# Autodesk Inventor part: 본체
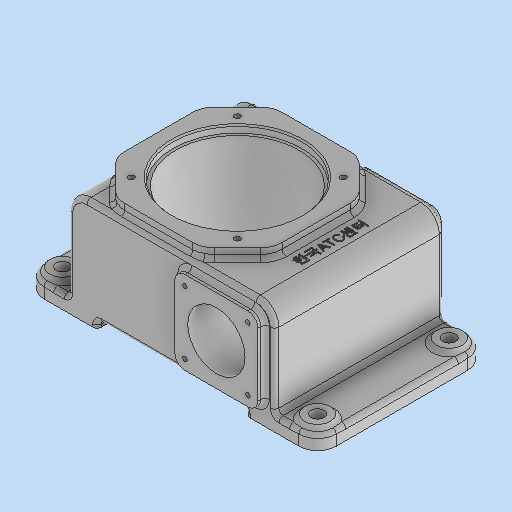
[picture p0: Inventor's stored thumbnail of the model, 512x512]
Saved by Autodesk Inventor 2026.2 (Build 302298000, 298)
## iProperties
Created: 2026-02
Part Number: 본체
Material: 일반
Document SubType Name: Modeling
Designer: PC2-07
Density: 1 g/cm^3
Appearance: 기본값
Author: PC2-07
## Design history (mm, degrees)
sketch "스케치1"
  geometry: L1 (102, -59)-(-102, -59); L2 (-102, -59)-(-102, 59); L3 (-102, 59)-(102, 59); L4 (102, 59)-(102, -59); L5 (102, -59)-(-102, 59); L6 (-102, -59)-(102, 59); L7 (-52, 59)-(-52, -59); L8 (52, 59)-(52, -59); 1 further point
  constraints: 16 end point, 4 point on line, 3 perpendicular, 2 midpoint, 2 parallel, 1 horizontal
  dimensions: "d0" = 118 distance between parallel lines of L1 L3; "d1" = 204 distance between parallel lines of L4 L2; "d2" = 50 distance between parallel lines of L2 L7; "d3" = 50 distance between parallel lines of L4 L8
extrude "돌출1" new body sketch "스케치1" distance "d4" = 10; taper "d5" = 0 deg
node "작업 평면1"
sketch "스케치2"
  geometry: L1 (72, -59)-(-72, -59); L2 (-72, -59)-(-72, 59); L3 (-72, 59)-(72, 59); L4 (72, 59)-(72, -59); L5 (72, -59)-(-72, 59); L6 (-72, -59)-(72, 59); 1 further point
  constraints: 12 end point, 2 midpoint, 2 parallel, 1 horizontal, 1 perpendicular
  dimensions: "d7" = 118 distance between parallel lines of L1 L3; "d8" = 144 distance between parallel lines of L4 L2
extrude "돌출2" join sketch "스케치2" distance "d9" = 70; taper "d10" = 0 deg
node "작업 평면2"
sketch "스케치3"
  geometry: L1 (-7.359, 69)-(-65.359, 69); L2 (-65.359, 69)-(-65.359, 11); L3 (-65.359, 11)-(-7.359, 11); L4 (-7.359, 11)-(-7.359, 69); L5 (-7.359, 69)-(-65.359, 11); L6 (-65.359, 69)-(-7.359, 11); 2 further points
  constraints: 12 end point, 2 midpoint, 2 parallel, 1 horizontal, 1 perpendicular
  dimensions: "d12" = 40 vertical distance of point (0, 0) point (-36.359, 40); "d13" = 58 distance between parallel lines of L3 L1; "d14" = 58 distance between parallel lines of L4 L2
extrude "돌출3" join sketch "스케치3" distance "d15" = 128; taper "d16" = 0 deg
sketch "스케치4"
  geometry: L1 (-68, -30)-(-68, 30); L2 (-68, 22.782)-(-35.782, 55); L3 (-43, 55)-(17, 55); L4 (9.782, 55)-(42, 22.782); L5 (42, 30)-(42, -30); L6 (42, -22.782)-(9.782, -55); L7 (17, -55)-(-43, -55); L8 (-35.782, -55)-(-68, -22.782); L9 (42, -30)-(17, -55); L10 (-68, -30)-(-43, -55); L11 (-68, 30)-(-43, 55); L12 (17, 55)-(42, 30); L13 (102, -59)-(102, 59) reference; 6 further points
  constraints: 24 end point, 16 point on line, 1 horizontal alignment, 1 midpoint, 1 vertical, 17 other
  dimensions: "d17" = 110 distance between parallel lines of L7 L3; "d18" = 25 distance of L5.end point (42, -55); "d19" = 25 distance of L7.start point (42, -55) (= d18); "d20" = 25 distance of L1.start point (-68, -55); "d21" = 25 distance of L7.end point (-68, -55) (= d20); "d22" = 25 distance of L1.end point (-68, 55) (= d20); "d23" = 25 distance of L3.start point (-68, 55) (= d22); "d24" = 25 distance of L3.end point (42, 55) (= d20); "d25" = 25 distance of L5.start point (42, 55) (= d24); "d97" = 115 distance from line of L13 point (-13, 0)
extrude "돌출4" join sketch "스케치4" distance "d26" = 7; taper "d27" = 0 deg
sketch "스케치5"
  geometry: L1 (102, -59)-(102, 59) reference; C1 r 9 at (89, -46); 1 further point
  constraints: 1 centre point
  dimensions: "d28" = 18 diameter of C1; "d29" = 46 vertical distance of C1.centre point (0, 0); "d123" = 13 distance from line of C1.centre L1
extrude "돌출5" join sketch "스케치5" distance "d31" = 3; taper "d32" = 0 deg
sketch "스케치6"
  geometry: C1 r 9 at (0, 0) reference; 2 further points
  constraints: 1 coincident
hole "구멍1" sketch "스케치6" at (0, 0) diameter "d33" = 9; stored, may be unused: countersink angle "d37" = 90 deg, drill point angle "d39" = 120 deg; dims "d34" = 6, "d35" = 4, "d36" = 2, "d38" = 10
sketch "스케치7"
  geometry: L1 (7.359, 11)-(7.359, 69) reference; 2 further points
  dimensions: "d46" = 40 vertical distance of point (0, 0) point (36.359, 40); "d47" = 29 distance from line of L1 point (36.359, 40)
hole "구멍2" sketch "스케치7" at (36.359, 40) diameter "d48" = 40; stored, may be unused: countersink angle "d52" = 90 deg, drill point angle "d54" = 120 deg; dims "d49" = 6, "d50" = 4, "d51" = 2, "d53" = 8
sketch "스케치8"
  geometry: L1 (13, 82)-(13, 11); L2 (13, 11)-(-7, 11); L3 (-65.359, 11)-(-7.359, 11) reference; L4 (-7, 11)-(-7, 22); L5 (-7, 22)-(-12, 22); L6 (-12, 22)-(-18, 16); L7 (-18, 16)-(-30, 16); L8 (-30, 16)-(-30, 77); L9 (-30, 77)-(-32, 77); L10 (-32, 77)-(-32, 82); L11 (-32, 82)-(13, 82); L12 (-42, 82)-(-17, 82) reference; L13 (-17, 82)-(43, 82) reference; 1 further point
  constraints: 20 end point, 5 perpendicular, 2 collinear, 1 midpoint, 1 parallel, 1 vertical
  dimensions: "d55" = 40 diameter of L4 L1; "d58" = 50 diameter of L5.end L1; "d59" = 5 distance between parallel lines of L11 L9; "d60" = 90 diameter of L10 L1; "d61" = 86 diameter of L8 L1; "d62" = 45 deg angle of L4 L6; "d63" = 66 distance between parallel lines of L7 L11; "d64" = 6 distance between parallel lines of L5 L7; "d65" = 11 distance between parallel lines of L5 L2
revolve "회전1" sketch "스케치8" stored, may be unused: angle "d66" = 90 deg
sketch "스케치9"
  geometry: C1 r 20 at (36.359, 40) reference; 2 further points
  dimensions: "d67" = 22 horizontal distance of C1.centre point (14.359, 62); "d68" = 22 horizontal distance of C1.centre point (14.359, 62)
hole "구멍3" sketch "스케치9" at (14.359, 62) diameter "d69" = 3.242; stored, may be unused: countersink angle "d73" = 90 deg, drill point angle "d75" = 118 deg; dims "d70" = 8, "d71" = 4, "d72" = 2, "d74" = 10
sketch "스케치10"
  geometry: C1 r 20 at (-13, 0) reference; 2 further points
  dimensions: "d98" = 37 horizontal distance of point (-50, -37) C1.centre; "d99" = 37 horizontal distance of point (-50, -37) C1.centre
hole "구멍4" sketch "스케치10" at (-50, -37) diameter "d84" = 4.134; stored, may be unused: countersink angle "d88" = 90 deg, drill point angle "d90" = 118 deg; dims "d85" = 10, "d86" = 4, "d87" = 2, "d89" = 12
fillet "모깎기5" dims "d112" = 13
chamfer "모따기1" distance "d105" = 1; stored, may be unused: second distance "d106" = 2, angle "d107" = 45 deg
fillet "모깎기1" dims "d108" = 1.5
fillet "모깎기2" dims "d109" = 3
fillet "모깎기3" dims "d110" = 15
fillet "모깎기4" dims "d111" = 13
fillet "모깎기6" dims "d113" = 3
fillet "모깎기7" dims "d114" = 3
fillet "모깎기9" dims "d116" = 3
fillet "모깎기10" dims "d117" = 3
fillet "모깎기11" dims "d118" = 3
fillet "모깎기12" dims "d119" = 3
fillet "모깎기13" dims "d120" = 7
fillet "모깎기14" dims "d121" = 3
fillet "모깎기15" dims "d122" = 3
sketch "스케치12"
  geometry: L1 (48.5, -22.5)-(48.5, 22.5); L2 (48.5, 22.5)-(55.5, 22.5); L3 (55.5, 22.5)-(55.5, -22.5); L4 (55.5, -22.5)-(48.5, -22.5); L5 (52, -22.5)-(52, 22.5); L6 (48.5, 0)-(55.5, 0); C1 r 20 at (-13, 0) reference; 3 further points
  constraints: 6 midpoint, 4 end point, 1 horizontal alignment, 2 other
  dimensions: "d124" = 45 distance of L2.end L3.end; "d125" = 7 distance of L3.end L1.start; "d126" = 65 distance of point (52, 0) C1.centre
feature "엠보싱2" sketch "스케치12" dims "d127" = 0.5, "d128" = 0
node "솔리드1"
pattern_linear "직사각형 패턴1" dims "d42" = 178, "d45" = 92
pattern_linear "직사각형 패턴2" dims "d78" = 44, "d81" = 44
mirror "미러1"
pattern_linear "직사각형 패턴3" dims "d93" = 74, "d96" = 74
feature "A9D066F2-1C7D-4E18-AEED-F7BC21143FA4" dims "d33" = 9, "d34" = 6, "d35" = 4, "d36" = 2, "d37" = 90 deg, "d38" = 10, "d39" = 120 deg
other parameters: "d6" = 5, "d11" = -64
